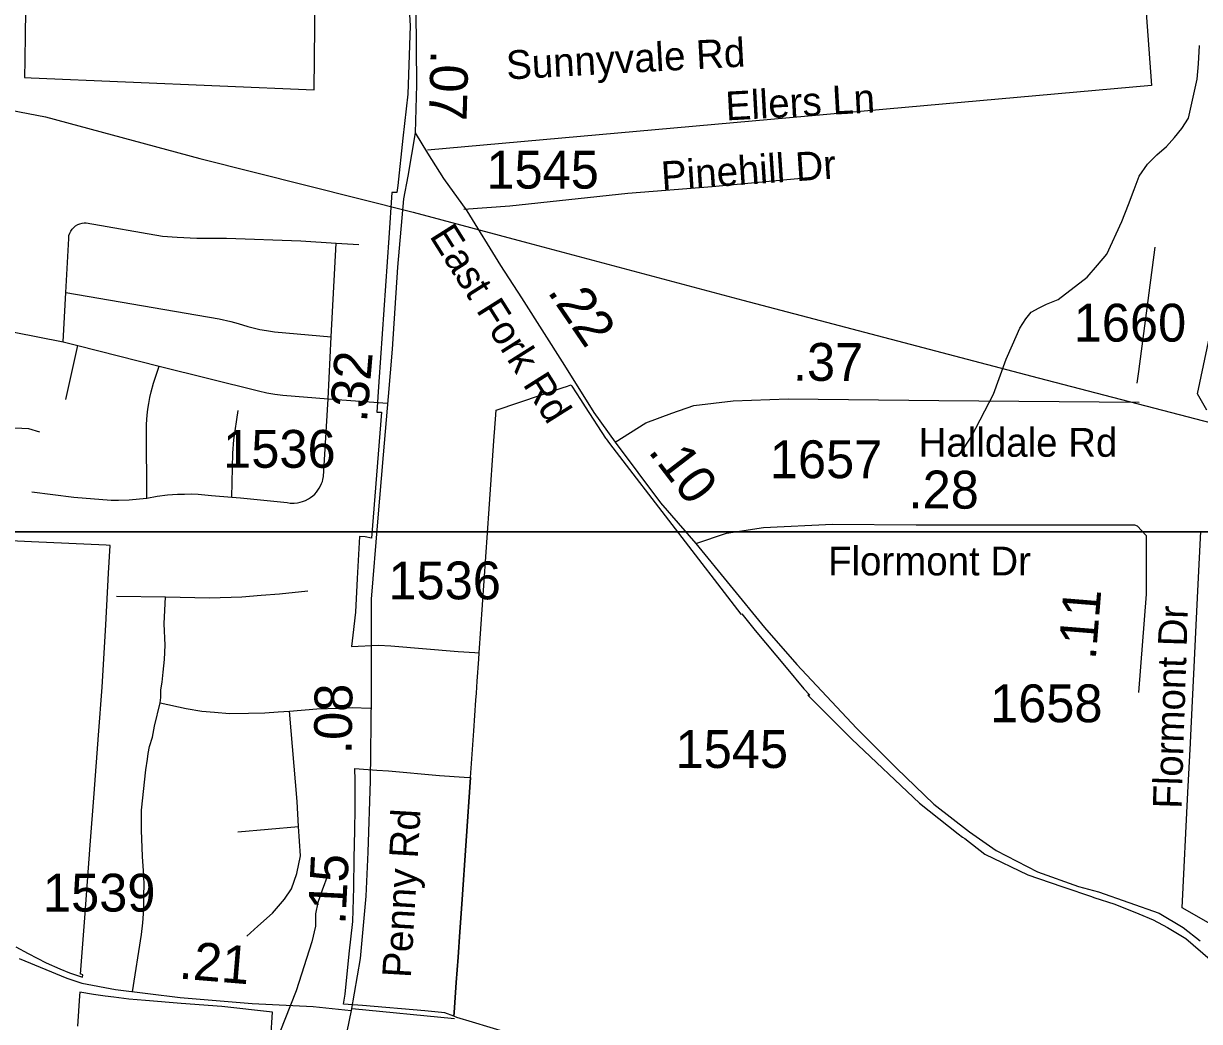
# Model space of a CAD drawing. Extents: x 1662474 to 1856135, y 779280 to 917889.
# Drawn here: x 1715474 to 1719362, y 824971 to 828268 of the extents above; entities that cross this region are included whole.
import ezdxf

# ---------------------------------------------------------------- set-up
doc = ezdxf.new("R2010")
doc.units = 0
for name, color, linetype in [('Exist Boundary Political City Limit New', 7, 'Continuous'), ('Exist Boundary Political City Limit New Hole', 7, 'Continuous'), ('Exist Hydrographic Misc Water Feature', 7, 'Continuous'), ('Exist Road Non-System Type 51', 7, 'Continuous'), ('Exist Road Non-System Type 51 Label', 7, 'Continuous'), ('Exist Road Secondary Mileage Hundredths English Label', 7, 'Continuous'), ('Exist Road Secondary Mileage Tenths English Label', 7, 'Continuous'), ('Exist Road Secondary Type 51 Attributed', 7, 'Continuous'), ('Exist Road Secondary Type 51 Label', 7, 'Continuous'), ('Exist Road Secondary Type 51 Number Label', 7, 'Continuous'), ('Exist Utilities Electrical Transmission Line', 7, 'Continuous'), ('Map Preparation Boundary City Limit Buffer Line', 7, 'Continuous'), ('Map Preparation Inset Cut Line', 7, 'Continuous')]:
    doc.layers.add(name, color=color, linetype=linetype)

msp = doc.modelspace()

# ---------------------------------------------------------------- linework, layer by layer
at = {"layer": 'Exist Boundary Political City Limit New'}
for points in [[(1716980.4, 826189.1), (1717013.5, 826664.6), (1717030.2, 826904.2), (1717031.1, 826917.2), (1717036.2, 826990.4), (1717261.9, 827066.7), (1717265.6, 827067.9), (1717284.4, 827074.2), (1717287.2, 827069.6), (1717315.4, 827026), (1717331, 827001.9), (1717398.1, 826897.7), (1717399.8, 826895.2), (1717411.6, 826879.9)], [(1717411.6, 826879.9), (1717845.9, 826316.9), (1717848.9, 826317.2), (1717893.1, 826262.5), (1717994.9, 826140.7), (1718053.9, 826069.9), (1718073.5, 826048.8), (1718066.5, 826049.1), (1718211.9, 825903.7), (1718436.5, 825691.6), (1718563.6, 825590.7), (1718577.9, 825579.4), (1718585.4, 825575), (1718651.8, 825523.4), (1718794.4, 825454.8), (1718906.9, 825416.6), (1718913.1, 825414.4), (1719004.9, 825383.2), (1719012.4, 825380.6), (1719082.1, 825358.1), (1719160.8, 825326.7), (1719208, 825306.4), (1719256.2, 825280.6), (1719315.9, 825244.6), (1719397.1, 825175.9)], [(1716951.9, 825776.6), (1716962.5, 825930.9), (1716969.5, 826031.8), (1716971.2, 826055.8), (1716974, 826095.4), (1716979, 826168.1), (1716980.4, 826189.1)], [(1716897.2, 824988.4), (1716898, 825000), (1716904.9, 825099.2), (1716910.6, 825183), (1716916.5, 825266.9), (1716922.8, 825357.9), (1716951.9, 825776.6)], [(1717215.9, 824631.6), (1717216, 824637.5), (1717217.4, 824679.9), (1717220.2, 824769.9), (1717223.4, 824869.8), (1717223.5, 824872.3), (1717224, 824889.2), (1717131.6, 824916.8), (1717016.8, 824951.2), (1716958.1, 824968.7), (1716907.1, 824983.9), (1716897.2, 824988.4)]]:
    msp.add_lwpolyline(points, dxfattribs=at)
at = {"layer": 'Exist Boundary Political City Limit New Hole'}
for points in [[(1715481, 828306.4), (1715479.9, 828232.4), (1715478.6, 828147.1), (1715477.9, 828089.6), (1715499.2, 828088.8), (1716435, 828048.4), (1716438.9, 828361.6)], [(1716747.1, 828354), (1716752.6, 828260.1), (1716745.2, 828035.1), (1716728.5, 827889.4), (1716711.5, 827733), (1716708.9, 827709.6), (1716691.9, 827710.1), (1716681.5, 827560.1), (1716648.4, 827083.6), (1716642.6, 826984.4), (1716657.4, 826983.8), (1716625, 826567.2), (1716604, 826571.8), (1716584.8, 826572.8), (1716577.6, 826434.8), (1716572.1, 826323.2), (1716562.8, 826247.3), (1716558.1, 826209.7), (1716648, 826214.2), (1716688.6, 826211.8), (1716910.9, 826193.2), (1716966.1, 826189.9), (1716980.4, 826189.1)], [(1719386.2, 826990.9), (1719355.5, 827044.4), (1719399.2, 827252.3)], [(1716980.4, 826189.1), (1717013.5, 826664.6), (1717030.2, 826904.2), (1717031.1, 826917.2), (1717036.2, 826990.4), (1717261.9, 827066.7), (1717265.6, 827067.9), (1717284.4, 827074.2), (1717287.2, 827069.6), (1717315.4, 827026), (1717331, 827001.9), (1717398.1, 826897.7), (1717399.8, 826895.2), (1717411.6, 826879.9)], [(1717411.6, 826879.9), (1717845.9, 826316.9), (1717848.9, 826317.2), (1717893.1, 826262.5), (1717994.9, 826140.7), (1718053.9, 826069.9), (1718073.5, 826048.8), (1718066.5, 826049.1), (1718211.9, 825903.7), (1718436.5, 825691.6), (1718563.6, 825590.7), (1718577.9, 825579.4), (1718585.4, 825575), (1718651.8, 825523.4), (1718794.4, 825454.8), (1718906.9, 825416.6), (1718913.1, 825414.4), (1719004.9, 825383.2), (1719012.4, 825380.6), (1719082.1, 825358.1), (1719160.8, 825326.7), (1719208, 825306.4), (1719256.2, 825280.6), (1719315.9, 825244.6), (1719397.1, 825175.9)], [(1719468, 825252.3), (1719304.1, 825346.5), (1719323.1, 825726.8), (1719331.4, 825890.7), (1719332.5, 825915.2), (1719337.1, 826006.8), (1719343.9, 826141.1), (1719350.8, 826279.6), (1719357.5, 826415.5), (1719366.1, 826589.4)], [(1715448.6, 825216.8), (1715489.9, 825195.6), (1715549.5, 825164.9), (1715594.8, 825144.2), (1715626.6, 825131.4), (1715649, 825123.2), (1715669.1, 825116.5), (1715670.1, 825125.2), (1715664.5, 825126.6), (1715663.1, 825126.9), (1715677.1, 825313.2), (1715695, 825552.7), (1715707.9, 825723.9), (1715722.2, 825916.1), (1715734.1, 826075.5), (1715746, 826281.3), (1715755.6, 826452.4), (1715760.8, 826543.4), (1715747.5, 826544.1), (1715500.4, 826555.6), (1715152.2, 826571.5)], [(1716897.2, 824988.4), (1716866.8, 824999.6), (1716800.5, 825005.3), (1716594.6, 825022.9), (1716532, 825027.6), (1716538.1, 825061.4), (1716551.1, 825194.1), (1716562.9, 825301.2), (1716566.6, 825413.3), (1716567.6, 825509.9), (1716569.2, 825601.1), (1716570.2, 825674.4), (1716570.4, 825767.6), (1716570, 825806.5), (1716642.4, 825800.9), (1716680.8, 825798.6), (1716849.5, 825782.9), (1716930.6, 825777.9), (1716951.9, 825776.6)], [(1716951.9, 825776.6), (1716922.8, 825357.9), (1716916.5, 825266.9), (1716910.6, 825183), (1716904.9, 825099.2), (1716898, 825000), (1716897.2, 824988.4)], [(1716286.4, 824829.5), (1716297.1, 825001.4), (1716129.6, 825019.6), (1715995.4, 825030.4), (1715877.1, 825040), (1715823, 825044.7), (1715773.1, 825050.6), (1715744.1, 825054), (1715705.9, 825059.6), (1715660.4, 825067.2), (1715659.4, 825054.9), (1715652.5, 824955.3)]]:
    msp.add_lwpolyline(points, dxfattribs=at)
at = {"layer": 'Exist Hydrographic Misc Water Feature'}
for points in [[(1718571.3, 826847.3), (1718607.5, 826903.1), (1718680.2, 827042.8), (1718723, 827158.5), (1718743.2, 827206.5), (1718767.2, 827260.9), (1718787.4, 827292.6), (1718805.7, 827314.4), (1718831.9, 827328.6), (1718855.5, 827340.4), (1718894, 827356), (1718990.5, 827430.4), (1719024.5, 827469.9), (1719054.8, 827506.2), (1719105.1, 827613.5), (1719127.3, 827669.7), (1719145.6, 827719.3), (1719162, 827763.4), (1719190, 827803.8), (1719220.2, 827833.6), (1719252.6, 827861.6), (1719278.6, 827891.5), (1719302.7, 827921.4), (1719325, 827955.4), (1719353.4, 828083.6), (1719357.8, 828135.2), (1719361.9, 828195.1)], [(1715528.8, 826918.3), (1715492.1, 826928.9), (1715445.9, 826931.4)], [(1716480, 825455.5), (1716461.8, 825404.1), (1716447.5, 825363.4), (1716439.2, 825325.8), (1716439.2, 825285.6), (1716426.9, 825234.1), (1716376, 825071.9), (1716303, 824887.9)]]:
    msp.add_lwpolyline(points, dxfattribs=at)
at = {"layer": 'Exist Road Non-System Type 51'}
for p, q in [((1716491.8, 827232.4), (1716507.5, 827542.5)), ((1716507.5, 827542.5), (1716582.9, 827537.8)), ((1715605.6, 827215.7), (1715614, 827379.5)), ((1715605.6, 827215.7), (1715654, 827204.2)), ((1715614.4, 827025.9), (1715654, 827204.2)), ((1715654, 827204.2), (1715922.8, 827136.2)), ((1716481.5, 827027.8), (1716491.8, 827232.4)), ((1716481.5, 827027.8), (1716677.9, 827013.4)), ((1715781.2, 826375.4), (1715943.5, 826373.8)), ((1716183.1, 825597.1), (1716383.1, 825614.4)), ((1716561.1, 825013.1), (1716898.6, 824980.6))]:
    msp.add_line(p, q, dxfattribs=at)
for points in [[(1719176, 828424.9), (1719202.8, 828063.2), (1716809.9, 827849)], [(1716930.1, 827654.2), (1717082.4, 827665.9), (1717472.1, 827707.6), (1717750.9, 827729.6), (1718092.5, 827761.6)], [(1715614, 827379.5), (1715623.6, 827557.2), (1715624.6, 827567.4), (1715627, 827575), (1715630.9, 827582.1), (1715635.1, 827588.4), (1715640.4, 827594.2), (1715646.6, 827599.9), (1715653.5, 827603.9), (1715660.9, 827606.5), (1715668.1, 827608.6), (1715674.6, 827609.2), (1715681.6, 827609.4), (1715933.2, 827565.4), (1715982.4, 827561.9), (1716047.6, 827558.8), (1716112.9, 827558.5), (1716145.1, 827559.2), (1716390.5, 827549.9), (1716507.5, 827542.5)], [(1719155.6, 827079.3), (1719161.5, 827117.9), (1719215.1, 827528.9)], [(1715614, 827379.5), (1716121.6, 827292.1), (1716159.5, 827283.2), (1716184.4, 827277.1), (1716215.4, 827267.2), (1716233, 827262.4), (1716255, 827256.9), (1716277.6, 827253.2), (1716304.4, 827249.6), (1716491.8, 827232.4)], [(1715308.4, 827262.9), (1715322.5, 827263.5), (1715343.2, 827263.2), (1715350.1, 827263.2), (1715356.9, 827262.9), (1715363.8, 827262.4), (1715370.5, 827261.7), (1715377.1, 827261.1), (1715384.1, 827260.4), (1715391, 827259.2), (1715397.6, 827257.9), (1715404.4, 827256.9), (1715411.2, 827255.9), (1715431.1, 827251.2), (1715443.8, 827247.8), (1715605.6, 827215.7)], [(1715882.1, 826700), (1715880.5, 826925.4), (1715881.1, 826944.6), (1715883.5, 826974.2), (1715885, 826993.7), (1715888.1, 827012.6), (1715892.4, 827032.1), (1715896.5, 827051.2), (1715904, 827079.5), (1715922.8, 827136.2)], [(1715922.8, 827136.2), (1716250.9, 827054), (1716278.9, 827047.5), (1716305.4, 827042.8), (1716331.4, 827039.6), (1716481.5, 827027.8)], [(1716163.4, 826703.1), (1716191.5, 826701), (1716345.6, 826685.8), (1716355.4, 826683.7), (1716369.5, 826683.7), (1716380, 826684.2), (1716388.4, 826686.1), (1716397, 826688.4), (1716406.8, 826692.4), (1716415.9, 826697.1), (1716423.5, 826702.1), (1716430.6, 826707.1), (1716437.1, 826713.1), (1716442.9, 826719.7), (1716447.4, 826725.9), (1716452.1, 826732.8), (1716456.4, 826740.4), (1716459.8, 826748.2), (1716462.1, 826755.1), (1716463.9, 826761.7), (1716465.5, 826770.9), (1716481.5, 827027.8)], [(1716163.4, 826703.1), (1716166.4, 826848.2), (1716170, 826892.1), (1716184.1, 826989.4)], [(1715502, 826720.2), (1715640.9, 826703.1), (1715763.6, 826693.4), (1715788.4, 826693.4), (1715823.2, 826694.4), (1715858.1, 826697.4), (1715882.1, 826700)], [(1715882.1, 826700), (1715915.6, 826706.2), (1715950.4, 826710.8), (1715983.4, 826712.9), (1716006.2, 826713.4), (1716028.9, 826713.6), (1716051.6, 826712.4), (1716073.6, 826711), (1716096.2, 826708), (1716163.4, 826703.1)], [(1715943.5, 826373.8), (1716089.4, 826370.1), (1716195.8, 826374), (1716260, 826379), (1716320.9, 826383.2), (1716413.9, 826393.9)], [(1715926.1, 826023.1), (1715928.2, 826040.9), (1715928.2, 826065.9), (1715932.8, 826091.9), (1715935.9, 826124.7), (1715940.9, 826166.4), (1715942.1, 826213.9), (1715939.6, 826284.5), (1715943.5, 826373.8)], [(1715834.9, 825068.9), (1715864.2, 825258.5), (1715869.2, 825296.9), (1715870.8, 825326.2), (1715872.1, 825358.2), (1715872.1, 825390), (1715872.6, 825420.2), (1715872.4, 825453.5), (1715867.1, 825516.2), (1715864.2, 825602.9), (1715864.8, 825668.8), (1715878.9, 825802.6), (1715884.1, 825837.5), (1715886.9, 825856.2), (1715891.2, 825879.5), (1715900.5, 825910.2), (1715907.2, 825946.2), (1715926.1, 826023.1)], [(1715926.1, 826023.1), (1716011.8, 826004.4), (1716063.6, 825996.4), (1716105.4, 825992.4), (1716155, 825988.2), (1716217.8, 825988.9), (1716271.6, 825990.2), (1716316.1, 825994.2), (1716354, 825995.5)], [(1716354, 825995.5), (1716444.2, 826003.4), (1716515.6, 826006.2), (1716561.1, 826007.6), (1716620.9, 826006.2)], [(1716383.1, 825614.4), (1716379.4, 825697.2), (1716354, 825995.5)], [(1716212, 825252.2), (1716248.5, 825285), (1716297, 825328.4), (1716336.9, 825374.6), (1716359.8, 825408.4), (1716377.4, 825459.4), (1716390.1, 825517.9), (1716383.1, 825614.4)]]:
    msp.add_lwpolyline(points, dxfattribs=at)
at = {"layer": 'Exist Road Secondary Type 51 Attributed'}
for points in [[(1716771.4, 828313.1), (1716773.7, 828065.8), (1716769.4, 827906.4)], [(1716769.4, 827906.4), (1716745, 827763.8), (1716730.6, 827689.2), (1716710.5, 827463.3), (1716692.7, 827191.7), (1716679.3, 827035.9), (1716662.7, 826842.8), (1716644.5, 826621.4), (1716623.3, 826365.7), (1716624, 826047.5), (1716620.1, 825765.6), (1716612.8, 825529.7), (1716605.6, 825384.5), (1716587.4, 825179), (1716557.9, 825006.5)], [(1716769.4, 827906.4), (1716809.6, 827839.3), (1716862.9, 827756.4), (1716939.4, 827649.5), (1717051.3, 827468.4), (1717120.2, 827361.5), (1717262.9, 827137.9), (1717359.9, 826982.6), (1717429.8, 826884.5)], [(1717429.8, 826884.5), (1717531.7, 826948.8), (1717617, 826981.1), (1717690.2, 827005.4), (1717820.6, 827021.8), (1718001.6, 827028), (1718499.8, 827022.3), (1719162.2, 827016.7)], [(1717429.8, 826884.5), (1717580.1, 826684.1), (1717696.4, 826549.7)], [(1717696.4, 826549.7), (1717798.2, 826584.3), (1717920, 826602.5), (1718149, 826613.6), (1718425.5, 826611.3), (1719146.3, 826611.3), (1719155.2, 826608.3)], [(1719155.2, 826608.3), (1719185.8, 826576.2), (1719185.8, 826382.9), (1719159.5, 826057.9)], [(1717696.4, 826549.7), (1717923.5, 826272.2), (1718030.4, 826150.1), (1718228.1, 825939.3), (1718360, 825807.6), (1718483.1, 825689), (1718601.7, 825596.8), (1718689.6, 825535.3), (1718825.9, 825465), (1718962.1, 825416.7), (1719028, 825399.2), (1719228, 825328.9), (1719307.1, 825280.6), (1719364.3, 825236.7)], [(1715459.9, 825179.2), (1715617.8, 825113.8), (1715667.4, 825097.3), (1715778, 825075.9), (1715992.6, 825049.5), (1716230.4, 825029.7), (1716431.9, 825019.8), (1716557.9, 825006.5)], [(1716557.9, 825006.5), (1716462.9, 824547.2), (1716406.2, 824240.6), (1716396.1, 824119.7), (1716392.4, 823979.2), (1716390.1, 823846.6), (1716400.5, 823765.1), (1716413.1, 823708.6), (1716483.1, 823479.7), (1716534.4, 823294.6), (1716551.2, 823248.6), (1716582.5, 823194.2), (1716654.4, 823103), (1716790.4, 822982.2), (1716931.5, 822881.5), (1717007.1, 822826.1), (1717077.6, 822750.5), (1717123, 822695.1), (1717163.3, 822624.6)]]:
    msp.add_lwpolyline(points, dxfattribs=at)
at = {"layer": 'Exist Utilities Electrical Transmission Line'}
msp.add_lwpolyline([(1712417.9, 828528.9), (1713335, 828365.2), (1714258, 828197.5), (1715139.2, 828038.3), (1715546.8, 827960), (1716057.7, 827822.5), (1716762.6, 827645.1), (1717141.7, 827543.1), (1717852.4, 827353.5), (1718828.7, 827097.1), (1719840.8, 826834.4)], dxfattribs=at)
at = {"layer": 'Map Preparation Boundary City Limit Buffer Line'}
for points in [[(1715481, 828306.4), (1715479.9, 828232.4), (1715478.6, 828147.1), (1715477.9, 828089.6), (1715499.2, 828088.8), (1716435, 828048.4), (1716438.9, 828361.6)], [(1716747.1, 828354), (1716752.6, 828260.1), (1716745.2, 828035.1), (1716728.5, 827889.4), (1716711.5, 827733), (1716708.9, 827709.6), (1716691.9, 827710.1), (1716681.5, 827560.1), (1716648.4, 827083.6), (1716642.6, 826984.4), (1716657.4, 826983.8), (1716625, 826567.2), (1716604, 826571.8), (1716584.8, 826572.8), (1716577.6, 826434.8), (1716572.1, 826323.2), (1716562.8, 826247.3), (1716558.1, 826209.7), (1716648, 826214.2), (1716688.6, 826211.8), (1716910.9, 826193.2), (1716966.1, 826189.9), (1716980.4, 826189.1)], [(1719386.2, 826990.9), (1719355.5, 827044.4), (1719399.2, 827252.3)], [(1716980.4, 826189.1), (1717013.5, 826664.6), (1717030.2, 826904.2), (1717031.1, 826917.2), (1717036.2, 826990.4), (1717261.9, 827066.7), (1717265.6, 827067.9), (1717284.4, 827074.2), (1717287.2, 827069.6), (1717315.4, 827026), (1717331, 827001.9), (1717398.1, 826897.7), (1717399.8, 826895.2), (1717411.6, 826879.9)], [(1716980.4, 826189.1), (1717013.5, 826664.6), (1717030.2, 826904.2), (1717031.1, 826917.2), (1717036.2, 826990.4), (1717261.9, 827066.7), (1717265.6, 827067.9), (1717284.4, 827074.2), (1717287.2, 827069.6), (1717315.4, 827026), (1717331, 827001.9), (1717398.1, 826897.7), (1717399.8, 826895.2), (1717411.6, 826879.9)], [(1717411.6, 826879.9), (1717845.9, 826316.9), (1717848.9, 826317.2), (1717893.1, 826262.5), (1717994.9, 826140.7), (1718053.9, 826069.9), (1718073.5, 826048.8), (1718066.5, 826049.1), (1718211.9, 825903.7), (1718436.5, 825691.6), (1718563.6, 825590.7), (1718577.9, 825579.4), (1718585.4, 825575), (1718651.8, 825523.4), (1718794.4, 825454.8), (1718906.9, 825416.6), (1718913.1, 825414.4), (1719004.9, 825383.2), (1719012.4, 825380.6), (1719082.1, 825358.1), (1719160.8, 825326.7), (1719208, 825306.4), (1719256.2, 825280.6), (1719315.9, 825244.6), (1719397.1, 825175.9)], [(1717411.6, 826879.9), (1717845.9, 826316.9), (1717848.9, 826317.2), (1717893.1, 826262.5), (1717994.9, 826140.7), (1718053.9, 826069.9), (1718073.5, 826048.8), (1718066.5, 826049.1), (1718211.9, 825903.7), (1718436.5, 825691.6), (1718563.6, 825590.7), (1718577.9, 825579.4), (1718585.4, 825575), (1718651.8, 825523.4), (1718794.4, 825454.8), (1718906.9, 825416.6), (1718913.1, 825414.4), (1719004.9, 825383.2), (1719012.4, 825380.6), (1719082.1, 825358.1), (1719160.8, 825326.7), (1719208, 825306.4), (1719256.2, 825280.6), (1719315.9, 825244.6), (1719397.1, 825175.9)], [(1719468, 825252.3), (1719304.1, 825346.5), (1719323.1, 825726.8), (1719331.4, 825890.7), (1719332.5, 825915.2), (1719337.1, 826006.8), (1719343.9, 826141.1), (1719350.8, 826279.6), (1719357.5, 826415.5), (1719366.1, 826589.4)], [(1715448.6, 825216.8), (1715489.9, 825195.6), (1715549.5, 825164.9), (1715594.8, 825144.2), (1715626.6, 825131.4), (1715649, 825123.2), (1715669.1, 825116.5), (1715670.1, 825125.2), (1715664.5, 825126.6), (1715663.1, 825126.9), (1715677.1, 825313.2), (1715695, 825552.7), (1715707.9, 825723.9), (1715722.2, 825916.1), (1715734.1, 826075.5), (1715746, 826281.3), (1715755.6, 826452.4), (1715760.8, 826543.4), (1715747.5, 826544.1), (1715500.4, 826555.6), (1715152.2, 826571.5)], [(1716951.9, 825776.6), (1716962.5, 825930.9), (1716969.5, 826031.8), (1716971.2, 826055.8), (1716974, 826095.4), (1716979, 826168.1), (1716980.4, 826189.1)], [(1716897.2, 824988.4), (1716866.8, 824999.6), (1716800.5, 825005.3), (1716594.6, 825022.9), (1716532, 825027.6), (1716538.1, 825061.4), (1716551.1, 825194.1), (1716562.9, 825301.2), (1716566.6, 825413.3), (1716567.6, 825509.9), (1716569.2, 825601.1), (1716570.2, 825674.4), (1716570.4, 825767.6), (1716570, 825806.5), (1716642.4, 825800.9), (1716680.8, 825798.6), (1716849.5, 825782.9), (1716930.6, 825777.9), (1716951.9, 825776.6)], [(1716897.2, 824988.4), (1716898, 825000), (1716904.9, 825099.2), (1716910.6, 825183), (1716916.5, 825266.9), (1716922.8, 825357.9), (1716951.9, 825776.6)], [(1716951.9, 825776.6), (1716922.8, 825357.9), (1716916.5, 825266.9), (1716910.6, 825183), (1716904.9, 825099.2), (1716898, 825000), (1716897.2, 824988.4)], [(1716286.4, 824829.5), (1716297.1, 825001.4), (1716129.6, 825019.6), (1715995.4, 825030.4), (1715877.1, 825040), (1715823, 825044.7), (1715773.1, 825050.6), (1715744.1, 825054), (1715705.9, 825059.6), (1715660.4, 825067.2), (1715659.4, 825054.9), (1715652.5, 824955.3)], [(1717215.9, 824631.6), (1717216, 824637.5), (1717217.4, 824679.9), (1717220.2, 824769.9), (1717223.4, 824869.8), (1717223.5, 824872.3), (1717224, 824889.2), (1717131.6, 824916.8), (1717016.8, 824951.2), (1716958.1, 824968.7), (1716907.1, 824983.9), (1716897.2, 824988.4)]]:
    msp.add_lwpolyline(points, dxfattribs=at)
at = {"layer": 'Map Preparation Inset Cut Line'}
for points in [[(1731035.7, 826588.1), (1668486.3, 826588.1), (1668486.3, 870408.9), (1731035.7, 870408.9)], [(1731035.7, 782767.4), (1668486.3, 782767.4), (1668486.3, 826588.1), (1731035.7, 826588.1)]]:
    msp.add_lwpolyline(points, close=True, dxfattribs=at)

# ---------------------------------------------------------------- texts
at = {"layer": 'Exist Road Non-System Type 51 Label'}
for s, rotation, p in [('Ellers Ln', 3.1358, (1717797.4, 827947.6)), ('Pinehill Dr', 3.8603, (1717585.2, 827717))]:
    msp.add_text(s, height=95, rotation=rotation, dxfattribs=at).set_placement(p)
at = {"layer": 'Exist Road Secondary Mileage Hundredths English Label'}
for s, rotation, p in [('.32', 85.0972, (1716609.1, 826948.1)), ('.08', 89.2084, (1716558.8, 825853.7)), ('.15', 87.1352, (1716538.2, 825289.3)), ('.21', 355.239, (1715985.9, 825112.8))]:
    msp.add_text(s, height=125, rotation=rotation, dxfattribs=at).set_placement(p)
at = {"layer": 'Exist Road Secondary Mileage Tenths English Label'}
for s, rotation, p in [('.07', 268.3743, (1716820.4, 828180.9)), ('.22', 304.3473, (1717203.9, 827382)), ('.37', 359.7473, (1718017.5, 827087.8)), ('.10', 307.4531, (1717536.3, 826854)), ('.28', 359.5222, (1718399.4, 826666.6)), ('.11', 85.3611, (1719018.3, 826163.6))]:
    msp.add_text(s, height=125, rotation=rotation, dxfattribs=at).set_placement(p)
at = {"layer": 'Exist Road Secondary Type 51 Label'}
for s, rotation, p in [('Sunnyvale Rd', 3.1358, (1717072.3, 828082.9)), ('East Fork Rd', 302.2254, (1716814.3, 827565.9)), ('Flormont Dr', 88.1827, (1719302.2, 825672.6)), ('Penny Rd', 86.6781, (1716754.6, 825113.2))]:
    msp.add_text(s, height=95, rotation=rotation, dxfattribs=at).set_placement(p)
for s, p in [('Halldale Rd', (1718433.3, 826836.5)), ('Flormont Dr', (1718133.8, 826444.5))]:
    msp.add_text(s, height=95, dxfattribs=at).set_placement(p)
at = {"layer": 'Exist Road Secondary Type 51 Number Label'}
for s, p in [('1545', (1717004.4, 827722.5)), ('1660', (1718945.8, 827217)), ('1536', (1716134.3, 826800.1)), ('1657', (1717941.3, 826765.7)), ('1536', (1716680.5, 826365.4)), ('1658', (1718669.2, 825959.3)), ('1545', (1717629.8, 825808.2)), ('1539', (1715538.6, 825333.8))]:
    msp.add_text(s, height=125, dxfattribs=at).set_placement(p)

doc.saveas('drawing.dxf')
